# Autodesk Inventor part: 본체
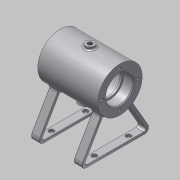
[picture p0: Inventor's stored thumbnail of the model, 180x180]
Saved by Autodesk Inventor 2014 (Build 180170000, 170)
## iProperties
Created: 2016-03
Part Number: 본체
Material: 알루미늄 6061
Document SubType Name: Modeling
Designer: SCD-A15
Density: 2.71 g/cm^3
Appearance: 알루미늄 - 평지
Mass: 213.318 g
Surface Area: 333.813 cm^2
Volume: 78.715 cm^3
Author: SCD-A15
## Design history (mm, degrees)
sketch "스케치2"
  geometry: L1 (0, 0)-(70, 0); L2 (0, 0)-(0, 26); L3 (0, 26)-(70, 26); L4 (70, 26)-(70, 0); L5 (0, 16)-(12, 16); L6 (12, 16)-(12, 14); L7 (12, 14)-(14, 14); L8 (14, 14)-(14, 21); L9 (14, 21)-(56, 21); L10 (56, 21)-(56, 14); L11 (56, 14)-(58, 14); L12 (58, 14)-(58, 16); L13 (58, 16)-(70, 16)
  constraints: 26 end point, 7 parallel, 5 perpendicular, 2 point on line, 1 horizontal
  dimensions: "d0" = 70 distance of L1.start L1.end; "d1" = 32 diameter of L5.start L1; "d2" = 28 diameter of L6.end L1; "d3" = 52 diameter of L2.end L1; "d4" = 42 diameter of L8.end L1; "d5" = 28 diameter of L11.end L1; "d6" = 32 diameter of L12.end L1; "d7" = 12 distance of L5.start L5.end; "d8" = 42 distance of L8.end L9.end; "d9" = 12 distance of L12.end L13.end; "d10" = 2 distance of L6.end L7.end
revolve "회전1" sketch "스케치2" stored, may be unused: angle "d11" = 90 deg
node "작업 평면2"
  node "작업 평면1"
sketch "스케치3"
  geometry: L1 (35, 26)-(35, -26) reference; L2 (-35, 26)-(-35, -26) reference; L3 (35, -26)-(-35, -26) reference; C1 r 5 at (0, 0); 2 further points
  constraints: 1 centre point, 1 horizontal alignment, 1 midpoint, 1 vertical alignment
  dimensions: "d13" = 10 diameter of C1
extrude "돌출1" join sketch "스케치3" stored distance "d14" = 10; taper "d15" = 0 deg
node "작업 평면4"
  node "작업 평면3"
sketch "스케치4"
  geometry: L1 (-42.594, -65)-(42.594, -65); L2 (0, 0)-(0, -65); L3 (-42.594, -65)-(-16.613, -20); L4 (-16.613, -20)-(-14.015, -21.5); L5 (-14.015, -21.5)-(-37.398, -62); L6 (-37.398, -62)-(37.398, -62); L7 (37.398, -62)-(14.015, -21.5); L8 (14.015, -21.5)-(16.613, -20); L9 (16.613, -20)-(42.594, -65); 2 further points
  constraints: 18 end point, 4 perpendicular, 2 midpoint, 2 parallel, 1 horizontal, 1 vertical alignment, 2 other
  dimensions: "d17" = 65 distance from line of L1 point (0, 0); "d18" = 3 distance between parallel lines of L6 L1; "d19" = 3 distance between parallel lines of L5 L3; "d20" = 3 distance between parallel lines of L9 L7; "d21" = 30 deg angle of L3 L2; "d22" = 30 deg angle of L9 L2; "d23" = 45 distance from line of L8.end L1; "d24" = 45 distance from line of L3.end L1
extrude "돌출2" join sketch "스케치4" distance "d27" = 10; taper "d28" = 0 deg
node "작업 평면10"
sketch "스케치6"
  geometry: L1 (0, 0)-(7.506, -28.012); L2 (0, 0)-(0, -37.231); L3 (7.506, -28.012)-(5.796, -21.629); L4 (5.796, -21.629)-(0, -23.182); L5 (0, -23.182)-(1.71, -29.565); L6 (1.71, -29.565)-(7.506, -28.012); C1 r 26 at (0, 0) reference; 1 further point
  constraints: 12 end point, 2 parallel, 2 point on line, 1 perpendicular, 1 vertical
  dimensions: "d35" = 15 deg angle of L1 L2; "d36" = 29 distance of L1.end point (0, 0); "d37" = 6 distance between parallel lines of L3 L5
revolve "회전2" sketch "스케치6" stored, may be unused: angle "d38" = 90 deg
sketch "스케치7" dims "d39" = 42
  geometry: C1 r 16 at (0, 0) reference; C2 r 26 at (0, 0) reference; 2 further points
  constraints: 2 vertical alignment, 1 coincident, 2 other
hole "구멍1" sketch "스케치7" at (0, 21) diameter "d40" = 3.242; stored, may be unused: countersink angle "d44" = 90 deg, drill point angle "d46" = 118 deg; dims "d41" = 8, "d42" = 4, "d43" = 2, "d45" = 10
hole "구멍2" diameter "d52" = 5.188; stored, may be unused: countersink angle "d56" = 90 deg, drill point angle "d58" = 118 deg; dims "d50" = 10, "d51" = 10, "d53" = 8, "d54" = 4, "d55" = 2, "d57" = 10
hole "구멍3" diameter "d61" = 5.188; stored, may be unused: countersink angle "d65" = 90 deg, drill point angle "d67" = 118 deg; dims "d59" = 10, "d60" = 10, "d62" = 8, "d63" = 4, "d64" = 2, "d66" = 10
fillet "모깎기2" dims "d73" = 0.3
fillet "모깎기3" dims "d74" = 3
fillet "모깎기4" dims "d75" = 2
fillet "모깎기5" dims "d76" = 2
fillet "모깎기6" dims "d77" = 5
fillet "모깎기7" dims "d78" = 2.5
chamfer "모따기1" distance "d79" = 1; stored, may be unused: second distance "d80" = 2, angle "d81" = 45 deg
fillet "모깎기8" dims "d82" = 3
fillet "모깎기9" dims "d83" = 0.5
fillet "모깎기10" dims "d84" = 3
fillet "모깎기11" dims "d88" = 0.5
sketch "스케치9"
  geometry: L1 (0, 66.135)-(9, 66.135) reference; L2 (9, 0)-(0, 0) reference; L3 (4.5, 66.135)-(4.5, 0); C1 r 3 at (4.5, 53.068); C2 r 3 at (4.5, 13.068); 1 further point
  constraints: 2 centre point, 2 end point, 2 midpoint, 2 point on line, 1 equal radius
  dimensions: "d89" = 40 distance of C2.centre C1.centre; "d90" = 20 vertical distance of point (-5.5, 33.068) C1.centre; "d91" = 6 diameter of C1
extrude "돌출4" cut sketch "스케치9" stored distance "d92" = 10; taper "d93" = 0 deg
node "작업 평면12"
  node "작업 평면11"
sketch "스케치10"
  geometry: L1 (35, 26)-(-35, 26) reference; 3 further points
  constraints: 1 horizontal alignment, 1 midpoint, 1 vertical alignment, 1 other
feature "엠보싱1" sketch "스케치10" dims "d95" = 0.5, "d96" = 0
node "솔리드1"
mirror "대칭1"
pattern_circular "원형 패턴1" dims angle "d48" = 360 deg
mirror "대칭2"
mirror "대칭4"
node "투영된 루프1"
other parameters: "d12" = 3, "d94" = 90 deg
